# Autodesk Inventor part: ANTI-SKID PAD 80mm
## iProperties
Created: 2007-03
Part Number: ANTI-SKID PAD 80mm
Material: Rubber
Document SubType Name: Modeling
Designer: Andy Moles
Density: 0.93 g/cm^3
Mass: 25.5703 g
Surface Area: 96.6938 cm^2
Volume: 27.495 cm^3
Author: Andy Moles
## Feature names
1. Extrusion1
2. Extrusion2
3. Fillet1
